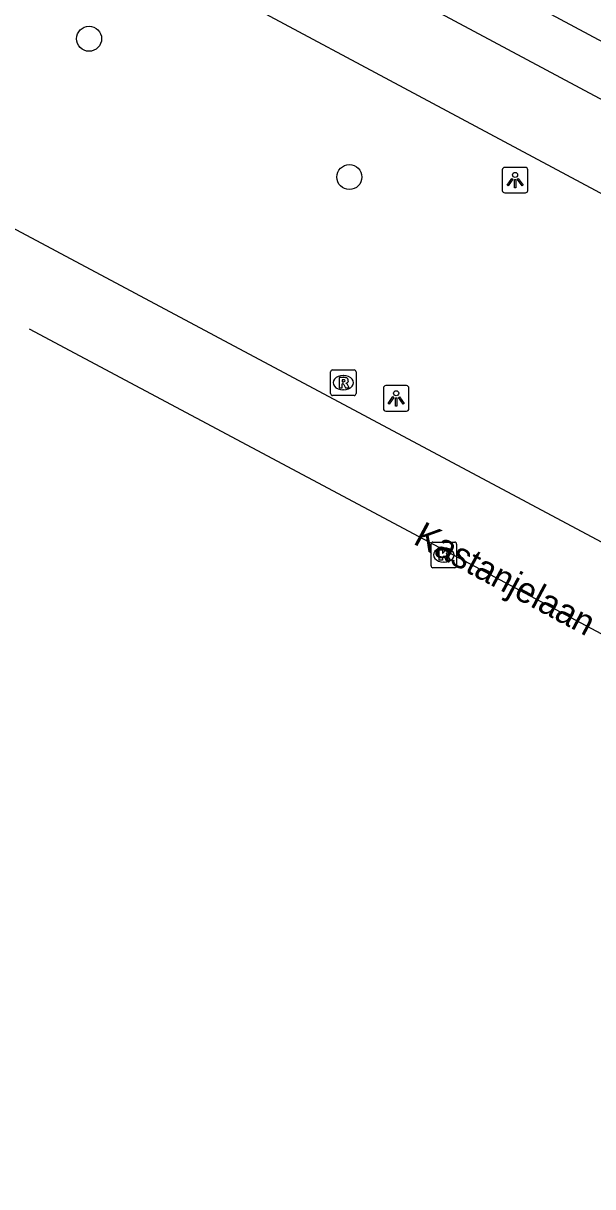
# Model space of a CAD drawing. Extents: x 159489 to 160304, y 383826 to 384530.
# Drawn here: x 160020.81 to 160043.09, y 383834.38 to 383879.92 of the extents above; entities that cross this region are included whole.
import ezdxf

# ---------------------------------------------------------------- set-up
doc = ezdxf.new("R2010")
doc.units = 0
for name, color, linetype in [('IMGEO_Boom', 7, 'Continuous'), ('IMGEO_Kolk', 7, 'Continuous'), ('IMGEO_Lichtpunt', 7, 'Continuous'), ('IMGEO_Openbare_ruimte_label', 7, 'Continuous'), ('IMGEO_Rijbaan_lokaal_gesloten', 7, 'Continuous'), ('IMGEO_Rijbaan_lokaal_open', 7, 'Continuous'), ('IMGEO_Rioolput', 7, 'Continuous')]:
    doc.layers.add(name, color=color, linetype=linetype)

msp = doc.modelspace()

# ---------------------------------------------------------------- linework, layer by layer
at = {"layer": 'IMGEO_Boom'}
for centre in [(160023.383, 383879.308), (160033.566, 383873.897)]:
    msp.add_circle(centre, 0.489, dxfattribs=at)
at = {"layer": 'IMGEO_Kolk'}
for p, q in [((160036.837, 383859.609), (160037.689, 383859.609)), ((160036.762, 383858.683), (160036.762, 383859.535)), ((160037.25, 383859.389), (160037.275, 383859.389)), ((160037.763, 383859.535), (160037.763, 383858.683)), ((160037.273, 383858.829), (160037.248, 383858.829)), ((160037.689, 383858.609), (160036.837, 383858.609))]:
    msp.add_line(p, q, dxfattribs=at)
for points in [[(160036.837, 383859.609), (160037.689, 383859.609)], [(160036.762, 383858.683), (160036.762, 383859.535)], [(160037.083, 383859.309), (160037.206, 383859.309), (160037.206, 383859.158), (160037.336, 383859.309), (160037.5, 383859.309), (160037.354, 383859.158), (160037.507, 383858.909), (160037.355, 383858.909), (160037.27, 383859.073), (160037.206, 383859.006), (160037.206, 383858.909), (160037.083, 383858.909), (160037.083, 383859.309)], [(160037.763, 383859.535), (160037.763, 383858.683)], [(160037.689, 383858.609), (160036.837, 383858.609)]]:
    msp.add_lwpolyline(points, dxfattribs=at)
for centre, start, end in [((160036.839, 383859.533), 91.552, 178.448), ((160036.839, 383859.533), 91.552, 178.448), ((160037.687, 383859.533), 1.552, 88.448), ((160037.687, 383859.533), 1.552, 88.448), ((160036.839, 383858.685), 181.552, 268.448), ((160036.839, 383858.685), 181.552, 268.448), ((160037.687, 383858.685), 271.552, 358.448), ((160037.687, 383858.685), 271.552, 358.448)]:
    msp.add_arc(centre, 0.0765, start, end, dxfattribs=at)
for centre, major_axis, ratio, start_param, end_param in [((160037.249, 383859.109), (-0.387, 0.002), 0.722429, 4.712389, 7.853982), ((160037.274, 383859.109), (-0.39, 0.002), 0.717154, 1.570796, 4.712389)]:
    msp.add_ellipse(centre, major_axis=major_axis, ratio=ratio, start_param=start_param, end_param=end_param, dxfattribs=at)
at = {"layer": 'IMGEO_Lichtpunt'}
for p, q in [((160039.551, 383874.181), (160039.551, 383873.374)), ((160039.551, 383874.181), (160039.551, 383873.374)), ((160040.453, 383874.276), (160039.645, 383874.276)), ((160040.453, 383874.276), (160039.645, 383874.276)), ((160040.547, 383873.374), (160040.547, 383874.181)), ((160040.547, 383873.374), (160040.547, 383874.181)), ((160039.645, 383873.28), (160040.453, 383873.28)), ((160039.645, 383873.28), (160040.453, 383873.28)), ((160034.898, 383865.638), (160034.898, 383864.831)), ((160034.898, 383865.638), (160034.898, 383864.831)), ((160035.8, 383865.733), (160034.992, 383865.733)), ((160035.8, 383865.733), (160034.992, 383865.733)), ((160035.894, 383864.831), (160035.894, 383865.638)), ((160035.894, 383864.831), (160035.894, 383865.638)), ((160034.992, 383864.737), (160035.8, 383864.737)), ((160034.992, 383864.737), (160035.8, 383864.737))]:
    msp.add_line(p, q, dxfattribs=at)
for points in [[(160039.925, 383873.845), (160039.964, 383873.817), (160039.776, 383873.555), (160039.738, 383873.582), (160039.925, 383873.845)], [(160040.027, 383873.797), (160040.074, 383873.797), (160040.074, 383873.475), (160040.027, 383873.475), (160040.027, 383873.797)], [(160040.137, 383873.817), (160040.175, 383873.844), (160040.362, 383873.582), (160040.323, 383873.554), (160040.137, 383873.817)], [(160035.272, 383865.302), (160035.311, 383865.274), (160035.123, 383865.012), (160035.085, 383865.039), (160035.272, 383865.302)], [(160035.374, 383865.254), (160035.421, 383865.254), (160035.421, 383864.932), (160035.374, 383864.932), (160035.374, 383865.254)], [(160035.484, 383865.274), (160035.522, 383865.301), (160035.709, 383865.039), (160035.67, 383865.011), (160035.484, 383865.274)]]:
    msp.add_lwpolyline(points, dxfattribs=at)
for centre in [(160040.05, 383873.979), (160035.397, 383865.436)]:
    msp.add_circle(centre, 0.0994, dxfattribs=at)
for centre, start, end in [((160039.645, 383874.181), 90, 180), ((160039.645, 383874.181), 90, 180), ((160040.453, 383874.181), 0, 90), ((160040.453, 383874.181), 0, 90), ((160039.645, 383873.374), 180, 270), ((160039.645, 383873.374), 180, 270), ((160040.453, 383873.374), 270, 0), ((160040.453, 383873.374), 270, 360), ((160034.992, 383865.638), 90, 180), ((160034.992, 383865.638), 90, 180), ((160035.8, 383865.638), 0, 90), ((160035.8, 383865.638), 0, 90), ((160034.992, 383864.831), 180, 270), ((160034.992, 383864.831), 180, 270), ((160035.8, 383864.831), 270, 0), ((160035.8, 383864.831), 270, 360)]:
    msp.add_arc(centre, 0.0946, start, end, dxfattribs=at)
at = {"layer": 'IMGEO_Rijbaan_lokaal_gesloten'}
for points in [[(160078.438, 383858.214), (159972.412, 383914.912)], [(159970.742, 383912.143), (160053.478, 383867.874), (160056.095, 383866.396), (160058.689, 383864.804)], [(160055.851, 383852.975), (159969.898, 383898.866)], [(160084.017, 383834.381), (160021.053, 383867.95)]]:
    msp.add_lwpolyline(points, dxfattribs=at)
at = {"layer": 'IMGEO_Rijbaan_lokaal_open'}
msp.add_lwpolyline([(160076.629, 383861.444), (159976.343, 383915.107)], dxfattribs=at)
at = {"layer": 'IMGEO_Rioolput'}
for p, q in [((160032.83, 383865.422), (160032.83, 383866.274)), ((160032.905, 383866.348), (160033.757, 383866.348)), ((160033.318, 383866.128), (160033.343, 383866.128)), ((160033.831, 383866.274), (160033.831, 383865.422)), ((160033.341, 383865.568), (160033.316, 383865.568)), ((160033.757, 383865.348), (160032.905, 383865.348))]:
    msp.add_line(p, q, dxfattribs=at)
for points in [[(160032.83, 383865.422), (160032.83, 383866.274)], [(160032.905, 383866.348), (160033.757, 383866.348)], [(160033.419, 383866.046), (160033.167, 383866.048), (160033.167, 383865.648)], [(160033.345, 383865.967), (160033.291, 383865.967), (160033.291, 383865.886)], [(160033.831, 383866.274), (160033.831, 383865.422)], [(160033.167, 383865.648), (160033.291, 383865.648), (160033.291, 383865.81), (160033.302, 383865.81)], [(160033.291, 383865.886), (160033.343, 383865.886)], [(160033.349, 383865.781), (160033.42, 383865.648), (160033.56, 383865.648), (160033.495, 383865.774)], [(160033.757, 383865.348), (160032.905, 383865.348)]]:
    msp.add_lwpolyline(points, dxfattribs=at)
for centre, radius, start, end in [((160032.907, 383866.272), 0.0765, 91.552, 178.448), ((160032.907, 383866.272), 0.0765, 91.552, 178.448), ((160033.351, 383865.871), 0.0964, 77.0061, 93.1865), ((160033.365, 383865.928), 0.0378, 276.6634, 79.6772), ((160033.418, 383865.936), 0.109, 350.3612, 89.416), ((160033.416, 383865.936), 0.112, 277.5842, 350.9817), ((160033.755, 383866.272), 0.0765, 1.552, 88.448), ((160033.755, 383866.272), 0.0765, 1.552, 88.448), ((160033.301, 383865.757), 0.0533, 26.0293, 88.6989), ((160033.327, 383866.075), 0.19, 274.7715, 282.9687), ((160033.4, 383865.721), 0.108, 29.5134, 73.7905), ((160032.907, 383865.424), 0.0765, 181.552, 268.448), ((160032.907, 383865.424), 0.0765, 181.552, 268.448), ((160033.755, 383865.424), 0.0765, 271.552, 358.448), ((160033.755, 383865.424), 0.0765, 271.552, 358.448)]:
    msp.add_arc(centre, radius, start, end, dxfattribs=at)
for centre, major_axis, ratio, start_param, end_param in [((160033.317, 383865.848), (-0.387, 0.002), 0.722429, 4.712389, 7.853982), ((160033.342, 383865.848), (-0.39, 0.002), 0.717154, 1.570796, 4.712389)]:
    msp.add_ellipse(centre, major_axis=major_axis, ratio=ratio, start_param=start_param, end_param=end_param, dxfattribs=at)

# ---------------------------------------------------------------- texts
at = {"layer": 'IMGEO_Openbare_ruimte_label'}
msp.add_text('Kastanjelaan', height=1, rotation=331.8196, dxfattribs=at).set_placement((160036.023, 383859.566))

doc.saveas('drawing.dxf')
